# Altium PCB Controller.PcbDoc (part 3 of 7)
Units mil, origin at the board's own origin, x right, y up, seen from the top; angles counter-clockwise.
Board outline 9000 x 8000 mil, 6 copper layers (Top Layer, Layer 1, Layer 2, Layer 3, Layer 4, Bottom Layer), stack 61.699 mil thick; 761 components, 454 nets, 2369 pads, 1133 vias.
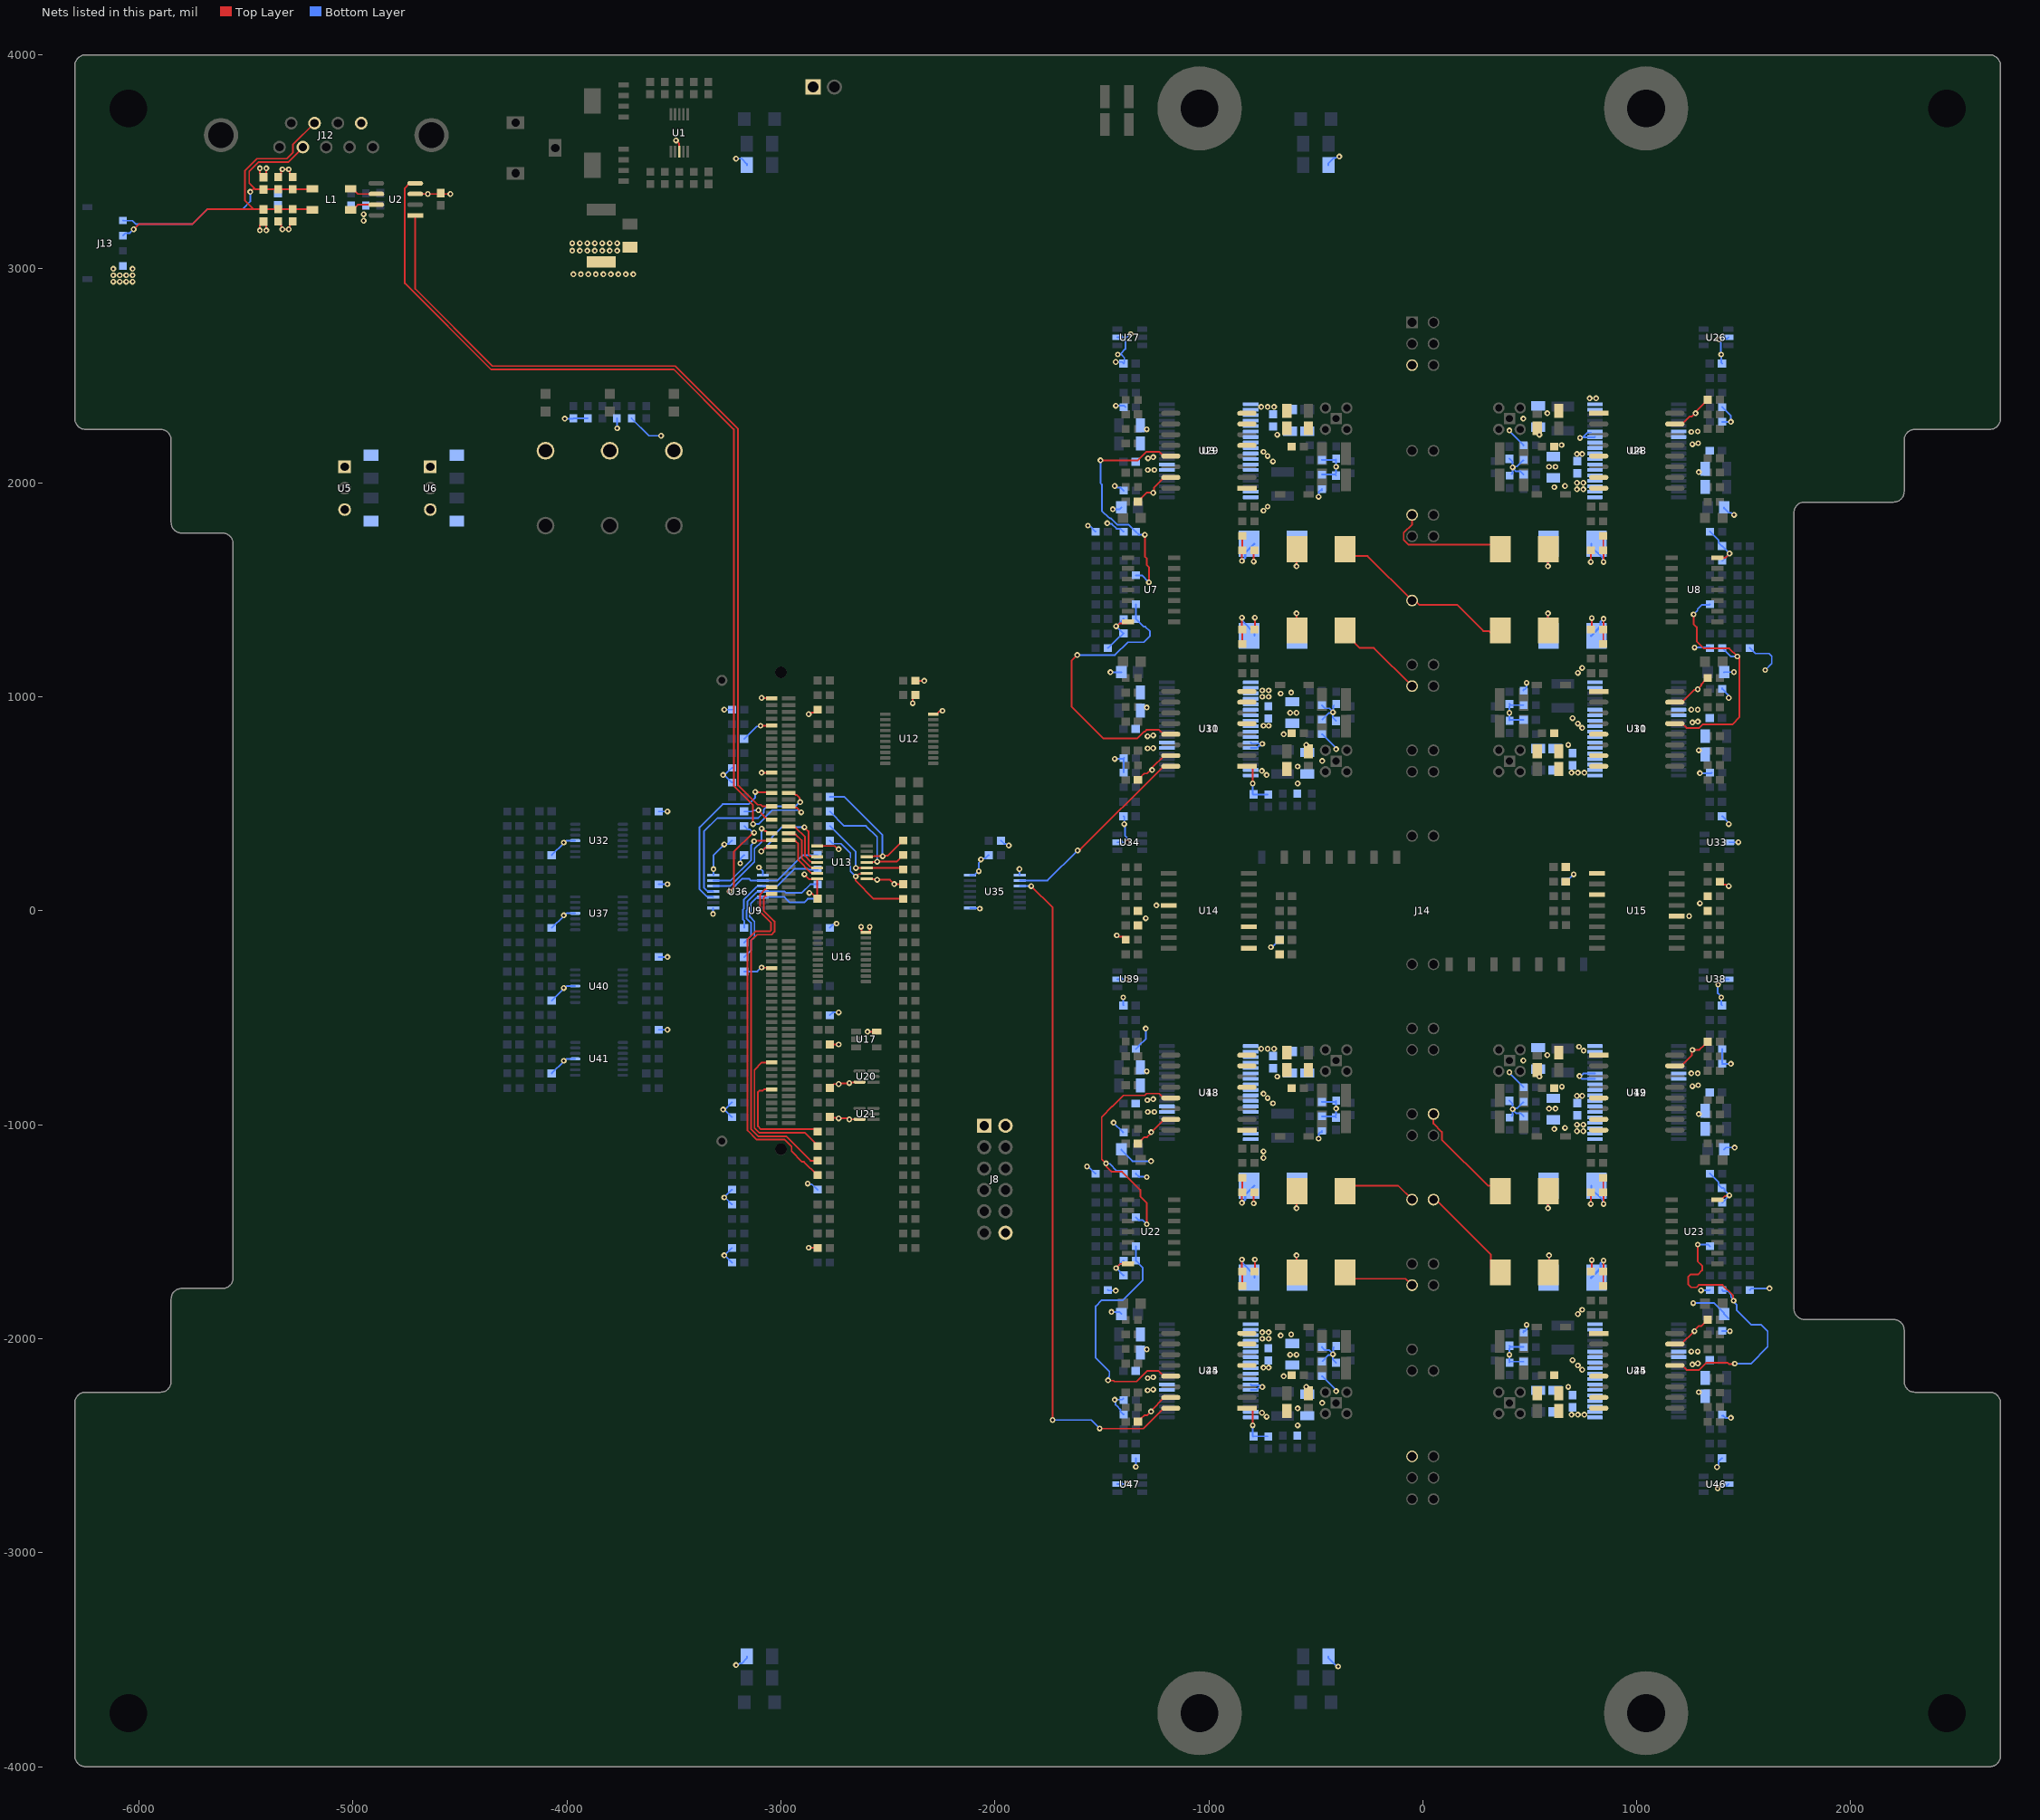
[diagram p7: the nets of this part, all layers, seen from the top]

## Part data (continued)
R171 R172: "RES SMD 4.7K OHM 1% 1/10W 0603", Case Code (Imperial)=0603, Case Code (Metric)=1608, Manufacturer="VISHAY DALE", Max Operating Temperature=155°C, Max Power Dissipation=100mW, Min Operating Temperature=-55°C, Package Quantity=5000, Power Rating=0.1W, Resistance=4.7kΩ, Resistor Type="Thick Film", Supplier Part Number 1=541-3004-6-ND, Temperature Coefficient=100ppm/°C, TOLERANCE=1%, Voltage Rating=75V
R174 R184 R212 R224 R306 R322 R362 R371: "RES SMD 107K OHM 0.1% 1/10W 0603", Case/Package=0603, Manufacturer=YAGEO, Power Rating=0.1W, Resistance=107kΩ, Temperature="-55°C to +155°C", Temperature Coefficient="25 ppm/°C", Temperature Range High=+155°C, Temperature Range Low=-55°C, TOLERANCE=0.001, Voltage Rating=75V
R175 R183 R213 R223 R307 R321 R363 R370: "RES SMD 30K OHM 0.5% 1/10W 0603", Case/Package=0603, Manufacturer=YAGEO, Power Rating=0.1W, Resistance=30kΩ, Temperature="-55°C to +155°C", Temperature Coefficient="50 ppm/°C", Temperature Range High=+155°C, Temperature Range Low=-55°C, TOLERANCE=0.005, Voltage Rating=75V
R176 R182 R214 R220 R311 R320 R364 R369: "RES SMD 49.9K OHM 1% 1/10W 0603", Case Code (Imperial)=0603, Case Code (Metric)=1608, Manufacturer=YAGEO, Max Operating Temperature=125°C, Max Power Dissipation=100mW, Min Operating Temperature=-55°C, Power Rating=0.1W, Resistance=49.9kΩ, Supplier Part Number 1=3100550, Temperature Coefficient=50ppm/°C, TOLERANCE=1%, Voltage Rating=75V, Voltage Rating (DC)=50V
R177 R181 R215 R219 R312 R318 R365 R368: "RES SMD 16.2K OHM 0.1% 1/10W", Case/Package=0603, Manufacturer=YAGEO, Power Rating=0.1W, Resistance=16.2kΩ, Temperature="-55°C to +155°C", Temperature Coefficient="25 ppm/°C", Temperature Range High=+155°C, Temperature Range Low=-55°C, TOLERANCE=0.001, Voltage Rating=75V
R186 R187 R208 R209 R324 R325 R358 R359: "RES 499 OHM 1% 1/8W 0805", Case Code (Imperial)=0805, Case Code (Metric)=2012, Manufacturer=YAGEO, Max Operating Temperature=155°C, Max Power Dissipation=0.13W, Min Operating Temperature=-55°C, Package Quantity=1, Power Rating=125mW, Resistance=499Ω, Resistor Type="Thick Film", Supplier Part Number 1=5825161, Temperature Coefficient=100ppm/°C, TOLERANCE=1%, Voltage Rating=150V
R237 R378: "RES SMD 0 OHM JUMPER 1/10W 0603", Case Code (Imperial)=0603, Case Code (Metric)=1608, Manufacturer="VISHAY DALE", Max Operating Temperature=155°C, Max Power Dissipation=100mW, Min Operating Temperature=-55°C, Package Quantity=10000, Power Rating=0.1W, Ratings=AEC-Q200, Resistance=0Ω, Resistor Type="Thick Film", Supplier Part Number 1=48P7902, Temperature Coefficient=100ppm/°C, TOLERANCE=1%, Voltage Rating=75V
R238 R379: "RES 5.1K OHM 1% 1/10W 0603", Case/Package=0603, Manufacturer=YAGEO, POWER=0.1W
R239 R240 R380 R381: "RES SMD 1.8K OHM 0.1% 1/5W 0603", Case Code (Imperial)=0603, Case Code (Metric)=1608, Manufacturer=PANASONIC, Max Operating Temperature=155°C, Max Power Dissipation=0.2W, Min Operating Temperature=-55°C, Resistance=1.8kΩ, Resistor Type="Thick Film", Temperature Coefficient=50ppm/°C, TOLERANCE=0.1%
R244 R246 R262 R264 R277 R279 R293 R300: "RES 27K OHM 1% 1/10W 0603", Case Code - mm=1608, Case/Package=0603, Manufacturer=YAGEO, Operating Temperature Range=-55Cto+155C, Package Description="2-Pin Surface Mount Device, Body 1.6 x 0.8 mm", Power Rating=0.1W, Temperature Coefficient=100PPM/C, TOLERANCE=1%, Voltage Rating=50V
R245 R247 R263 R265 R278 R280 R294 R301: library part CMP-2000-04305-1, "RES 1K OHM 5% 1/10W 0603", Case/Package=0603, Manufacturer=YAGEO, POWER=0.1W
R248 R256 R266 R271 R281 R287 R302 R310: "RES SMD 2.7K OHM 0.1% 1/10W 0603", Case/Package=0603, Manufacturer=YAGEO, Power Rating=0.1W, Resistance=2.7kΩ, Temperature="-55°C to +155°C", Temperature Coefficient="25 ppm/°C", Temperature Range High=+155°C, Temperature Range Low=-55°C, TOLERANCE=0.001, Voltage Rating=75V
R260 R267: "RES SMD 5.62KOHM 0.1% 1/10W 0603", Case/Package=0603, Manufacturer=PANASONIC, Max Operating Temperature=155°C, Min Operating Temperature=-55°C, Package Height=0.45mm, Package Length=1.6mm, Package Width=0.8mm, POWER=0.1W, Rated Temperature=85°C, Resistor Type="FIXED RESISTOR", Supplier Part Number=667-ERA-3AEB5621V, Temperature Coefficient (ppm/Cel)=25, TOLERANCE=0.1%, Working Voltage=75V
R284: "RES 5.49K OHM 1% 1/10W 0603", Case Code (Imperial)=0603, Case Code (Metric)=1608, Manufacturer=YAGEO, Max Operating Temperature=155°C, Max Power Dissipation=100mW, Min Operating Temperature=-55°C, Package Quantity=5000, Power Rating=0.1W, Resistance=5.49kΩ, Supplier Part Number 1=1172345, Temperature Coefficient=100ppm/°C, TOLERANCE=1%, Voltage Rating=50V
TP1 TP2 TP3: library part CMP-1672-00002-4, "PC TEST POINT MULTIPURPOSE RED", Case/Package=N/A, Colour=Red, Manufacturer=KEYSTONE, Package Quantity=100
TP4 TP5 TP6: library part CMP-1672-00003-4, "PC TEST POINT MULTIPURPOSE BLACK", Case/Package=N/A, Colour=Black, Manufacturer=KEYSTONE, Package Quantity=100
U1: "IC SURGE SUPPRESSION ADJ 10MSOP", Case/Package=10-MSOP, Manufacturer="ANALOG DEVICES", Supplier Part Number 1=505-LTC4368IMS-2#PBF-ND
U2: library part CMP-04872-000112-1, "IC TRANSCEIVER 1/1 8SOIC", Case/Package=8-SOIC, Manufacturer="TEXAS INSTRUMENTS"
U3 U4 U10 U11 U18 U19 U24 U25: library part CMP-00024-00019-13, "DGTL ISO 5.7KV 1CH GT DVR 16SOIC", Case/Package=16-SOIC, Manufacturer="TEXAS INSTRUMENTS", Max Operating Temperature=125°C, Min Operating Temperature=-40°C
U5: "DC DC CONVERTER 3.3V 3W", Case/Package=SIP, Manufacturer=RECOM, Max Input Voltage=28V, Max Operating Temperature=85°C, Max Output Current=1A, Max Output Power=3.3W, Max Output Voltage=3.3V, Max Power Dissipation=3W, Min Input Voltage=8V, Min Input Voltage (DC)=7V, Min Operating Temperature=-40°C, Package=3-SIP, Supplier Part Number 1=9176626
U6: "DC DC CONVERTER 5V 5W", Case/Package=SIP, Current - Output 1=1A, Manufacturer=RECOM, Max Input Voltage=28V, Max Operating Temperature=85°C, Max Output Voltage=5V, Max Power Dissipation=5W, Min Input Voltage=8V, Min Operating Temperature=-40°C, Package=3-SIP, Package Quantity=42, Supplier Part Number 1=1446013
U7 U8 U22 U23: "IC GATE AND 2CH 4-INP 14SOIC", Case/Package=8-SOIC, Manufacturer="TEXAS INSTRUMENTS"
U9: "EVAL BOARD FOR TMS320F280039C", Case/Package=N/A, Manufacturer="TEXAS INSTRUMENTS", Supplier Part Number 1=595-TMDSCNCD280039C
U12 U16: library part CMP-0440-01163-3, "IC BUF NON-INVERT 5.5V 20TSSOP", Case/Package=20-TSSOP, F @ Nom Voltage(Max)(Mhz)=110, Generic Part Number=SN74LV541AT, ICC @ Nom Voltage(Max)(mA)=0.02, Manufacturer="TEXAS INSTRUMENTS", Operating Temperature Range(C)="-40 to 125", Rating=Catalog, tpd @ Nom Voltage(Max)(ns)=7.9, Voltage(Nom)(V)=5
U13 U35 U36: "IC TRANSLATOR UNIDIR 14TSSOP", Case/Package=14-TSSOP, Manufacturer="TEXAS INSTRUMENTS"
U14 U15: "IC ISOLATED AMPLIFIER", Case/Package=16-SOIC, Manufacturer="TEXAS INSTRUMENTS"
U17: library part CMP-0384-02059-2, "IC OPAMP GP 1 CIRCUIT TSOT23-5", Amplifiers Per Package=1, Case/Package=TSOT-23-5, Generic Part Number=AD8615, Input Bias Current=200fA, Input Offset Voltage=80uV, Manufacturer="ANALOG DEVICES"
U20 U21: library part CMP-04895-000486-1, "IC OPAMP GP 1 CIRCUIT SC70-5", Case/Package=SC-70-5, Input Bias Current=1pA, Input Offset Voltage (Vos)=750uV, Manufacturer="TEXAS INSTRUMENTS", Max Operating Temperature=125°C, Min Operating Temperature=-40°C, Operating Supply Current=75uA, Output Current per Channel=15mA
U26 U27 U33 U34 U38 U39 U46 U47: library part CMP-0859-00232-4, "IC INVERTER 2CH 2-INP SOT23-6", Case/Package=SOT-23-6, F @ Nom Voltage(Max)(Mhz)=150, Generic Part Number=SN74LVC2G14, ICC @ Nom Voltage(Max)(mA)=0.01, Manufacturer="TEXAS INSTRUMENTS", Operating Temperature Range(C)="-40 to 125", Rating=Catalog, tpd @ Nom Voltage(Max)(ns)=9.5,5.7,5.4,4.3, Voltage(Nom)(V)=1.8,2.5,3.3,5
U28 U29 U30 U31 U42 U43 U44 U45: "DUAL DC DC CONVERTER 1.5W", Case/Package=36-BSSOP, Manufacturer="TEXAS INSTRUMENTS", Max Supply Voltage=27V, Min Supply Voltage=21V, Operating Temperature Range="-40°C to +150°C", Output Voltage=18-25/2.5-25V, Part Number=UCC14240DWNQ1
U32 U37 U40 U41: library part CMP-0384-01836-1, "IC CMOS 4 CIRCUIT 14TSSOP", Amplifiers Per Package=4, Case/Package=14-TSSOP, Generic Part Number=AD8618, Input Bias Current=200fA, Input Offset Voltage=23uV, Manufacturer="ANALOG DEVICES"

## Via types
v1: diameter 27, hole 13, Top Layer to Bottom Layer, tented both sides, 1133 vias

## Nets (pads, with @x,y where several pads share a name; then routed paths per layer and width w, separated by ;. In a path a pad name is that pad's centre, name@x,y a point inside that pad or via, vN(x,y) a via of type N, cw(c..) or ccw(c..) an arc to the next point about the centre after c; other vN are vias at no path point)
+3.3V: C44.1 C56.1 C64.1 C67.1 C114.1 C164.1 C165.1 J8.1 R41.2 R47.2 R137.2 R161.2 R168.2 R218.2 R230.2 R234.2 R242.2 R258.2 R272.2 R284.2 R289.2 R314.2 R319.2 R334.2 R335.2 R338.2 R348.2 R352.2 TP3.1 U5.3 U13.8 U13.14 U17.5 U20.5 U21.5 U35.8 U35.14 U36.8 U36.14 | length 2182.5
  Top Layer w8: v1(-2890,170) -2866.84,146.84 -2833.64,146.84 U13.14@-2831.25,149.23 -2831.25,58.67 -2832.2,58.67 -2853.2,79.67 -2863.21,79.67 v1(-2866.84,83.3) ; v1(-2870,-1575) -2829.62,-1575 R137.2@-2828.62,-1576 ; v1@-2866.84,86.84 v1@-2865.07,85.07 ; -2857.2,926.04 -2842.58,926.04 R47.2@-2828.62,940 ; -2831.65,113.37 -2831.65,113.75 ; U13.8@-2831.25,302.77 -2749.91,302.77 -2735.14,288 v1(-2730,288) ; C67.1@-2771.42,-964 -2767.92,-967.5 -2732.5,-967.5 v1(-2730,-970) -2690.14,-970 -2685.14,-975 v1(-2680,-975) -2679.8,-974.8 -2616.64,-974.8 U21.5@-2616.43,-975 ; C64.1@-2771.42,-828 -2770.47,-828 -2752.47,-810 v1(-2730,-810) -2727.5,-807.5 -2682.5,-807.5 v1(-2680,-805) -2676.89,-801.89 -2625.28,-801.89 U20.5@-2623.98,-800.59 ; C56.1@-2771.42,-624 -2770.42,-625 v1(-2730,-625) ; v1(-2595,-565) -2553.17,-565 U17.5@-2551.77,-563.6 ; R41.2@-2371.38,1076 -2370.38,1075 v1(-2330,1075)
  Bottom Layer w8: R168.2@-3698,2301.38 -3698,2300.47 -3617.53,2220 v1(-3560,2220) ; R289.2@-3571.38,-556 v1(-3530,-556) ; R272.2@-3571.38,-216 v1(-3530,-216) ; R258.2@-3571.38,124 v1(-3530,124) ; R242.2@-3571.38,464 v1(-3530,464) ; v1(-3317,-15) -3317,12.48 U36.8@-3316.25,13.23 ; U36.14@-3316.25,166.77 -3314.86,168.16 v1(-3314.86,194.59) -3314.86,260.14 v1(-3265,310) -3261.86,313.14 -3243.44,313.14 C164.1@-3228.58,328 ; v1(-3265,-1610) v1@-3263.53,-1610 ; v1(-3265,940) R218.2@-3228.62,940 ; R352.2@-3228.62,-1644 -3229.53,-1644 v1@-3263.53,-1610 ; R348.2@-3228.62,-1576 -3229.53,-1576 v1@-3263.53,-1610 ; R338.2@-3228.62,-1372 -3229.53,-1372 -3261.53,-1340 v1(-3265,-1340) -3265,-1339.47 -3229.53,-1304 R335.2@-3228.62,-1304 ; R319.2@-3228.62,-964 -3229.53,-964 -3260.89,-932.64 -3266.36,-932.64 v1(-3270,-929) -3266.36,-925.36 -3259.89,-925.36 -3229.53,-895 R314.2@-3228.62,-895 ; R234.2@-3228.62,600 -3229.53,600 -3260.89,631.36 -3266.36,631.36 v1(-3270,635) -3266.36,638.64 -3258.89,638.64 -3229.53,668 R230.2@-3228.62,668 ; v1(-2875,-1275) -2871.36,-1278.64 -2854.89,-1278.64 -2829.53,-1304 R334.2@-2828.62,-1304 ; v1(-2869.74,918.64) v1@-2866.11,915 ; R284.2@-2771.38,-488 -2758.38,-475 v1(-2730,-475) ; U35.8@-2116.25,13.23 -2114.64,11.61 -2071.61,11.61 v1(-2070,10) ; U35.14@-2116.25,166.77 -2095.5,166.77 -2077.27,185 v1(-2075,185) -2075,224.86 -2065,234.86 v1(-2065,240) -2059.86,240 -2054.72,245.14 -2043.44,245.14 C165.1@-2028.58,260
+5V: C4.1 C7.1 C18.1 C23.1 C26.1 C37.1 C42.1 C43.1 C45.1 C48.1 C49.1 C55.1 C69.1 C75.1 C86.1 C89.1 C90.1 C113.1 C115.1 C128.1 C142.1 C155.1 C157.1 C158.1 C162.1 C166.1 C168.1 C178.1 C181.1 C187.1 C193.1 C194.1 C195.1 C211.1 C231.1 C247.1 C269.1 C270.1 J8.2 J12.9 J14.005 J14.107 R69.2 R80.2 R160.2 R164.1 R165.1 R169.2 R173.2 R185.2 R186.2 R187.2 R188.2 R189.2 R190.2 R193.2 R202.2 R205.2 R206.2 R207.2 R208.2 R209.2 R211.2 R228.2 R231.1 R232.1 R295.1 R297.1 R303.2 R323.2 R324.2 R325.2 R327.2 R328.2 R329.2 R336.2 R350.2 R355.2 R356.2 R357.2 R358.2 R359.2 R361.2 R373.2 R374.1 R375.1 TP2.1 U2.3 U3.15 U4.15 U6.3 U7.14 U8.14 U9.48 U9.84 U9.98 U9.112 U9.120 U10.15 U11.15 U12.20 U13.1 U14.12 U15.12 U16.20 U18.15 U19.15 U22.14 U23.14 U24.15 U25.15 U26.5 U27.5 U32.4 U33.5 U34.5 U35.1 U36.1 U37.4 U38.5 U39.5 U40.4 U41.4 U46.5 U47.5 | length 8021
  Top Layer w8: U2.3@-4708.91,3350 v1(-4650,3350) -4593.58,3350 C4.1@-4590,3353.58 -4586.42,3350 v1(-4545,3350) ; v1(-3105,470) -3105,469.36 -3080.9,445.26 -3080.9,441.88 -3073.87,434.85 -3068.71,434.85 -3059.06,425.2 U9.84@-3042.32,425.2 ; v1(-3095,865) -3094.43,865.57 -3042.89,865.57 U9.112@-3042.32,866.14 ; v1(-3090,-265) -3088.64,-266.36 -3043.68,-266.36 U9.48@-3042.32,-267.72 ; v1(-3090,645) -3089.67,645.33 -3042.66,645.33 U9.98@-3042.32,645.67 ; v1(-3090,995) -3088.56,993.56 -3043.76,993.56 U9.120@-3042.32,992.13 ; v1(-2625,-75) -2622.42,-77.58 -2622.42,-96.97 -2618.54,-100.84 U16.20@-2602.8,-100.84 -2588.94,-100.84 -2585.07,-96.97 -2585.07,-75.07 v1(-2585,-75) ; U13.1@-2598.75,149.23 -2596.64,147.11 -2552.11,147.11 v1(-2550,145) -2490,145 v1(-2470,125) -2429.58,125 C42.1@-2428.58,124 ; v1(-2383.76,970) -2383.76,1005.66 C26.1@-2381.42,1008 ; U12.20@-2287.8,919.16 -2272.05,919.16 -2259.84,931.36 -2248.14,931.36 v1(-2245,934.5) ; v1(-1433.53,-1670) -1413.53,-1650 U22.14@-1377.25,-1650 ; v1(-1433.53,1330) -1428.39,1330 -1415.39,1343 -1384.25,1343 U7.14@-1377.25,1350 ; v1(-1430,-115) -1424.86,-115 -1417.81,-122.04 -1402.58,-122.04 R80.2@-1388.62,-136 ; C86.1@-1331.42,-2388 -1330.47,-2388 -1315.61,-2373.14 -1315.61,-2372.19 -1301.74,-2358.32 -1288.32,-2358.32 v1(-1270,-2340) -1270,-2336.68 -1208.32,-2275 U24.15@-1177.78,-2275 ; C69.1@-1331.42,-1088 -1330.47,-1088 -1315.61,-1073.14 -1315.61,-1072.19 -1301.74,-1058.32 -1288.32,-1058.32 -1269.78,-1039.78 v1(-1269.78,-1035) ; C37.1@-1331.42,612 -1330.47,612 -1315.61,626.86 -1315.61,627.81 -1301.74,641.68 -1288.32,641.68 v1@-1268.42,661.58 ; C18.1@-1331.42,1912 -1330.47,1912 -1315.61,1926.86 -1315.61,1927.81 -1288.42,1955 -1261.5,1955 v1(-1260,1953.5) ; v1@-1267.39,-1037.39 -1265,-1035 -1265,-1031.68 -1208.32,-975 U18.15@-1177.78,-975 ; v1(-1265,658.16) v1@-1268.42,661.58 ; v1@-1260,1955 -1256.36,1958.64 -1256.36,1976.96 -1208.32,2025 U3.15@-1177.78,2025 ; U10.15@-1177.78,725 -1208.32,725 -1265,668.32 -1265,665 v1@-1268.42,661.58 ; U25.15@1177.78,-2025 1208.32,-2025 1268.32,-1965 v1(1269.78,-1965) ; U19.15@1177.78,-725 1208.32,-725 1257.82,-675.5 1257.82,-652.18 v1(1260,-650) 1293.42,-650 1315.61,-627.81 1315.61,-626.86 1330.47,-612 C55.1@1331.42,-612 ; U11.15@1177.78,975 1211.65,975 1268.01,1031.36 1281.36,1031.36 v1(1285,1035) 1285,1035.92 1302.57,1053.49 1302.57,1059.15 1315.61,1072.19 1315.61,1073.14 1330.47,1088 C23.1@1331.42,1088 ; U4.15@1177.78,2275 1211.65,2275 1246.48,2309.83 1257.03,2309.83 1272.7,2325.5 v1(1275.24,2325.5) ; v1@1267.39,-1962.61 1288.32,-1941.68 1301.74,-1941.68 1315.61,-1927.81 1315.61,-1926.86 1330.47,-1912 C75.1@1331.42,-1912 ; v1@1275,2325.14 1278.82,2328.96 1278.82,2336.35 1330.47,2388 C7.1@1331.42,2388 ; U23.14@1377.25,-1350 1395,-1350 1411.36,-1333.64 1428.94,-1333.64 v1(1432.58,-1330) ; U8.14@1377.25,1650 1415,1650 1433.53,1668.53 v1(1433.53,1670) ; R69.2@1388.62,136 1402.58,122.04 1417.81,122.04 1424.86,115 v1(1430,115)
  Bottom Layer w8: C211.1@-4071.42,-760 -4070.47,-760 -4015,-704.53 v1(-4015,-701) -4009.86,-701 -4000.86,-692 U41.4@-3961.22,-692 ; C193.1@-4071.42,-420 -4070.47,-420 -4015,-364.53 v1(-4015,-361) -4009.86,-361 -4000.86,-352 U40.4@-3961.22,-352 ; C181.1@-4071.42,-80 -4070.47,-80 -4015,-24.53 v1(-4015,-21) -4009.86,-21 -4000.86,-12 U37.4@-3961.22,-12 ; C168.1@-4071.42,260 -4070.47,260 -4015,315.47 v1(-4015,319) -4009.86,319 -4000.86,328 U32.4@-3961.22,328 ; R169.2@-3766,2301.38 -3765,2300.38 v1(-3765,2255) ; v1(-3190.21,221.63) -3187.24,224.6 -3187.24,245.14 -3172.37,260 C166.1@-3171.42,260 ; C187.1@-3171.42,-284 -3110.06,-284 -3091.06,-265 v1(-3090,-265) -3093.64,-261.36 v1@-3093.64,-255.41 ; C155.1@-3171.42,464 -3135.88,464 -3130.5,469.38 -3105.62,469.38 v1(-3105,470) ; C142.1@-3171.42,804 -3170.47,804 -3113.11,861.36 -3098.64,861.36 v1(-3095,865) ; v1(-3102.5,202.5) -3083.75,183.75 U36.1@-3083.75,166.77 ; v1@-3090,640.47 v1(-3090,645) ; C178.1@-2771.42,-80 -2756.56,-65.14 -2745.28,-65.14 v1(-2740,-59.86) ; C162.1@-1971.42,328 -1956.56,313.14 -1948.28,313.14 -1940.14,305 v1(-1935,305) ; v1(-1885,195) -1885,168.02 U35.1@-1883.75,166.77 ; v1(-1569.5,-1195) -1565.86,-1198.64 -1558.89,-1198.64 -1529.53,-1228 R329.2@-1528.62,-1228 ; v1(-1565,1800) -1561.36,1796.36 -1553.89,1796.36 -1529.53,1772 R190.2@-1528.62,1772 ; v1(-1474.77,1811.46) -1471.14,1807.82 -1453.41,1807.82 -1431.55,1785.96 -1413.48,1785.96 -1399.53,1772 R189.2@-1398.62,1772 ; R357.2@-1471.38,-1772 -1468.38,-1775 v1(-1435,-1775) ; R207.2@-1471.38,1228 -1470.47,1228 -1417.34,1281.14 -1413.44,1281.14 C128.1@-1398.58,1296 -1399.53,1296 v1(-1433.53,1330) -1399.53,1364 R202.2@-1398.62,1364 ; v1(-1460,1115) R209.2@-1408.46,1115 ; v1(-1455,-1875) -1418.46,-1875 R359.2@-1408.46,-1885 ; v1(-1448.93,1876.94) -1416.52,1876.94 R187.2@-1408.46,1885 ; v1(-1445,-990) -1445,-991.53 -1401.53,-1035 R323.2@-1400,-1035 ; v1(-1440,710) R228.2@-1400,710 ; v1(-1439.5,1985) -1434.36,1985 -1426.31,1976.96 -1412.58,1976.96 R185.2@-1398.62,1963 ; v1(-1435,2565) -1405.58,2565 C90.1@-1398.58,2558 -1395,2561.58 -1395,2585 -1410,2600 v1@-1415,2600 ; v1(-1434.47,2360) -1395,2360 R165.1@-1390,2355 ; U47.5@-1428.07,-2680 -1427.46,-2679.38 -1381.85,-2679.38 v1(-1381.23,-2678.77) ; U39.5@-1428.07,-320 v1(-1385,-320) ; U34.5@-1428.07,320 v1(-1380,320) -1383.64,323.64 -1383.64,342.57 -1392.45,351.39 -1392.45,402.45 v1(-1395,405) -1395,438.42 C158.1@-1398.58,442 ; U27.5@-1428.07,2680 -1389.69,2680 ; v1(-1425.5,2600) -1423,2602.5 -1412.5,2602.5 -1389.69,2625.31 -1389.69,2680 ; R325.2@-1408.46,-1115 -1408.46,-1119.02 -1357.48,-1170 v1(-1270,-1170) ; R373.2@-1400,-2280 -1405,-2285 -1435,-2285 -1436.36,-2286.36 -1436.36,-2307.57 -1429.5,-2314.44 -1413.17,-2330.76 -1413.17,-2340.04 -1399.22,-2354 R375.1@-1398.62,-2354 ; v1(-1400,-405) -1400,-440.58 C195.1@-1398.58,-442 ; C247.1@-1398.58,-1704 -1399.53,-1704 v1(-1433.53,-1670) -1399.53,-1636 R350.2@-1398.62,-1636 ; R232.1@-1398.62,646 -1398.62,708.62 R228.2@-1400,710 ; R228.2@-1395,715 R228.2@-1400,710 ; v1(-1365,2695) -1370.14,2695 -1385.14,2680 -1389.69,2680 ; C270.1@-1341.42,-2558 -1341.23,-2558.19 v1(-1341.23,-2598.77) ; R328.2@-1341.38,-1228 -1327.42,-1241.96 -1293.04,-1241.96 v1(-1290,-1245) ; R297.1@-1341.38,-646 -1340.47,-646 -1326.52,-632.04 -1326.52,-631.14 -1295,-599.62 v1@-1295,-555 ; v1(1263.77,-1833.77) 1361.25,-1833.77 1408.46,-1880.98 R358.2@1408.46,-1885 R358.2@1429.15,-1905.68 ; v1(1270,1230) R206.2@1340.28,1230 ; v1(1295.24,643.17) 1348.17,643.17 R231.1@1350,645 ; v1(1300.48,-1774.42) 1337.8,-1774.42 1338.38,-1775 R356.2@1341.38,-1772 ; R327.2@1341.38,-1228 1342.28,-1228 1382.76,-1268.48 1382.76,-1281.14 1397.63,-1296 C231.1@1398.58,-1296 1406,-1296 1410,-1300 1410,-1306.47 1432.58,-1329.05 v1(1432.58,-1330) 1432.58,-1330.95 1399.53,-1364 R336.2@1398.62,-1364 ; R188.2@1341.38,1772 1342.28,1772 1382.76,1731.52 1382.76,1718.86 1397.63,1704 C115.1@1398.58,1704 1399.53,1704 v1(1433.53,1670) 1399.53,1636 R193.2@1398.62,1636 ; v1(1375,-2600) 1375,-2594.86 1382.76,-2587.09 1382.76,-2572.86 1397.63,-2558 C269.1@1398.58,-2558 ; v1(1377.98,-2700) 1383.12,-2700 1394.33,-2688.8 1419.28,-2688.8 U46.5@1428.07,-2680 ; R361.2@1398.62,-1963 1400.62,-1965 v1(1435,-1965) ; R295.1@1398.62,-646 1398.62,-708.62 R303.2@1400,-710 ; C194.1@1398.58,-442 1395,-438.42 1395,-401.67 1378.64,-385.3 1378.64,-346.36 v1(1380,-345) 1383.65,-345 1399.86,-328.8 1408.45,-328.8 1417.24,-320 U38.5@1428.07,-320 ; C157.1@1398.58,442 1399.53,442 1426.36,415.16 1426.36,408.77 v1(1430,405.14) ; R164.1@1398.62,2354 1399.53,2354 1439.5,2314.03 1439.5,2285.5 v1(1440,2285) ; C89.1@1398.58,2558 1394.53,2562.05 v1(1394.53,2600) 1392.45,2602.08 1392.45,2656.94 1384.53,2664.86 v1(1384.53,2670) 1388.16,2673.64 1421.71,2673.64 U26.5@1428.07,2680 ; R374.1@1400,-2360 1405.53,-2360 1415.53,-2370 v1(1440,-2370) ; R303.2@1400,-715 v1(1440,-715) ; R211.2@1400,1040 1400,1036.53 1426.36,1010.16 1426.36,998.64 v1(1430,995) ; R173.2@1400,2285 v1@1435,2285 ; R324.2@1408.46,-1115 1417.03,-1106.44 v1(1457.5,-1106.44) ; R208.2@1408.46,1115 1408.9,1115.44 v1(1454.5,1115.44) ; R186.2@1408.46,1885 1408.46,1880.98 1429.23,1860.22 1439.64,1860.22 1449.86,1850 v1(1455,1850) ; U33.5@1433.07,320 1433.14,320.07 1474.93,320.07 v1(1475,320.14) ; R355.2@1528.62,-1772 1535.62,-1765 v1(1620.5,-1765) ; R205.2@1528.62,1228 1529.53,1228 1555.35,1202.18 1619.13,1202.18 1631,1190.31 1631,1155.5 v1(1600.5,1125)
  other v1: -1440,-2285 -1295,-550 1395,-405 -1295,-35 1245,-25 -1245,25 1295,35 -4950,3225 -4950,3255
+12V: C6.1 C97.1 C99.1 C101.1 C102.1 C103.1 C106.1 C108.1 C112.1 C129.1 C135.1 C137.1 C140.1 C141.1 C146.1 C208.1 C213.1 C217.1 C220.1 C222.1 C227.1 C248.1 C254.1 C255.1 C258.1 C259.1 C263.1 J1.1 J8.12 J13.1 R13.2 R158.1 R159.1 R171.2 R172.2 R382.1 R383.1 TP1.1 U1.8 U5.1 U6.1 U28.6 U28.7 U29.6 U29.7 U30.6 U30.7 U31.6 U31.7 U42.6 U42.7 U43.6 U43.7 U44.6 U44.7 U45.6 U45.7 | length 447.3
  Top Layer w8: v1(-3490,3600) -3475,3585 U1.8@-3475,3547.91
  Bottom Layer w8: v1(-4010,2300) -3971.38,2300 R172.2@-3970,2301.38 R171.2@-3902,2301.38 ; v1(-3210,-3525) -3206.36,-3521.36 -3195.47,-3521.36 -3191.68,-3517.58 -3183.76,-3517.58 -3159.1,-3492.92 R383.1@-3159.1,-3485 ; v1(-3210,3515) -3183.76,3515 -3159.1,3490.34 R159.1@-3159.1,3485 ; R382.1@-440.9,-3485 -440.9,-3492.92 -405.31,-3528.51 -398.97,-3528.51 v1(-395.34,-3532.15) ; R158.1@-440.9,3485 -440.9,3492.92 -416.24,3517.58 -408.32,3517.58 -404.53,3521.36 -393.64,3521.36 v1(-390,3525)
  other v1: 1290,-2250 -1286.73,-2241.27 -1260.03,-2237.83 -1285.8,-2184.2 -1260,-2180 1260,-2120 1285.54,-2115.54 1254.98,-2060.18 1285,-2060 -1290,-2050 1290,-950 -1285,-940 -1255,-940 -1287.15,-884.88 -1260,-880 1260,-820 1287.15,-815.12 1255,-760 1285,-760 -1290,-750 1290,750 -1286.73,758.73 -1260,760.16 -1286.16,815.72 -1260,820 1260,880 1285.54,884.46 1255,940 1285,940 -1290,950 1290,2050 -1285,2060 -1255,2060 -1284.47,2114.47 -1260,2120 1260,2180 1287.15,2184.88 1254.49,2237.94 1285,2240 -1290,2250 -6120,2940 -6090,2940 -6060,2940 -6030,2940 -6120,2970 -6090,2970 -6060,2970 -6030,2970 -3970,2975 -3935,2975 -3900,2975 -3865,2975 -3830,2975 -3795,2975 -3760,2975 -3725,2975 -3690,2975 -6120,3000 -6030,3000 -3975,3085 -3940,3085 -3905,3085 -3870,3085 -3835,3085 -3800,3085 -3765,3085 -3975,3120 -3940,3120 -3905,3120 -3870,3120 -3835,3120 -3800,3120 -3765,3120
+15V_1P: C33.1 C144.1 C145.1 C148.1 R35.2 R212.2 U11.5 U30.28 U30.29 | length 95.3
  Top Layer w8: R35.2@786.38,1315 790,1318.62 v1(790,1367.52)
  Bottom Layer w8: R212.2@470,1035 477.04,1035 485,1042.96 v1(485,1065) ; R212.2@470.47,1029 R212.2@471.38,1029
  other v1: 680,775 745,855 725,875
+15V_1S: C82.1 C261.1 C262.1 C264.1 R139.2 R362.2 U25.5 U44.28 U44.29 | length 95.3
  Top Layer w8: R139.2@786.38,-1685 790,-1681.38 v1(790,-1632.48)
  Bottom Layer w8: R362.2@470,-1965 477.04,-1965 485,-1957.04 v1(485,-1935) ; R362.2@470.47,-1971 R362.2@471.38,-1971
  other v1: 680,-2225 745,-2145 725,-2125
+15V_2P: C35.1 C132.1 C134.1 C149.1 R34.2 R224.2 R238.2 U10.5 U31.28 U31.29 | length 153.6
  Top Layer w8: R34.2@-786.38,1315 -785,1316.38 v1(-785,1370)
  Bottom Layer w8: R224.2@-471.38,825 -470.47,825 -405,759.53 v1(-405,755)
  other v1: -585,595 -584.69,674.49 -745,865 -720.5,865 -615,1020
+15V_2S: C84.1 C251.1 C253.1 C265.1 R138.2 R371.2 R379.2 U24.5 U45.28 U45.29 | length 153.6
  Top Layer w8: R138.2@-786.38,-1685 -785,-1683.62 v1(-785,-1630)
  Bottom Layer w8: R371.2@-471.38,-2175 -470.47,-2175 -405,-2240.47 v1(-405,-2245)
  other v1: -585,-2405 -584.7,-2325.5 -745,-2135 -720.5,-2135 -615,-1980
+15V_3P: C11.1 C94.1 C95.1 C96.1 R32.2 R184.2 U3.5 U29.28 U29.29 | length 96.8
  Top Layer w8: v1(-790,1632.48) -790,1681.38 R32.2@-786.38,1685
  Bottom Layer w8: v1(-486.96,1935) -486.24,1935.73 -486.24,1957.04 -478.28,1965 R184.2@-470,1965 ; R184.2@-471.38,1971 R184.2@-470.47,1971
  other v1: -725,2125 -745,2145 -680,2225
+15V_3S: C60.1 C205.1 C206.1 C207.1 R129.2 R322.2 U18.5 U43.28 U43.29 | length 96.8
  Top Layer w8: v1(-790,-1367.52) -790,-1318.62 R129.2@-786.38,-1315
  Bottom Layer w8: v1(-486.96,-1065) -486.24,-1064.27 -486.24,-1042.96 -478.28,-1035 R322.2@-470,-1035 ; R322.2@-471.38,-1029 R322.2@-470.47,-1029
  other v1: -725,-875 -745,-855 -680,-775
+15V_4P: C9.1 C93.1 C104.1 C107.1 R33.2 R174.2 U4.5 U28.28 U28.29 | length 153.6
  Top Layer w8: v1(785,1630) 785,1683.62 R33.2@786.38,1685
  Bottom Layer w8: v1(405,2245) 405,2240.47 470.47,2175 R174.2@471.38,2175
  other v1: 615,1980 720.5,2135 745,2135 581.88,2325.5
+15V_4S: C58.1 C204.1 C218.1 C221.1 R130.2 R306.2 U19.5 U42.28 U42.29 | length 153.6
  Top Layer w8: v1(785,-1370) 785,-1316.38 R130.2@786.38,-1315
  Bottom Layer w8: v1(405,-755) 405,-759.53 470.47,-825 R306.2@471.38,-825
  other v1: 615,-1020 720.5,-865 745,-865 581.88,-674.5
-4V_1P: C33.2 C36.2 C130.2 C138.2 C144.2 C148.2 R215.1 R220.1 U11.8 U30.19 U30.20 U30.21 U30.22 U30.23 U30.24 U30.25 U30.26 U30.27 U30.30 U30.31 U30.35 U30.36 | length 196.4
  Bottom Layer w8: R220.1@405,890 408,893 C138.2@471.42,893 C138.2@471.42,893 ; R220.1@405,895 v1(405,925) C130.2@405,955 ; C130.2@405,966.42 410.42,961 R215.1@471.38,961
  other v1: 695,645 725,645 755,645 700,900 725,1111.5 745,1135
-4V_1S: C82.2 C85.2 C249.2 C256.2 C261.2 C264.2 R365.1 R369.1 U25.8 U44.19 U44.20 U44.21 U44.22 U44.23 U44.24 U44.25 U44.26 U44.27 U44.30 U44.31 U44.35 U44.36 | length 196.4
  Bottom Layer w8: R369.1@405,-2110 408,-2107 C256.2@471.42,-2107 C256.2@471.42,-2107 ; R369.1@405,-2105 v1(405,-2075) C249.2@405,-2045 ; C249.2@405,-2033.58 410.42,-2039 R365.1@471.38,-2039
  other v1: 695,-2355 725,-2355 755,-2355 700,-2100 725,-1885 745,-1865
-4V_2P: C32.2 C132.2 C133.2 C134.2 C139.2 C149.2 R214.1 R219.1 U10.8 U31.19 U31.20 U31.21 U31.22 U31.23 U31.24 U31.25 U31.26 U31.27 U31.30 U31.31 U31.35 U31.36 | length 306.3
  Bottom Layer w8: U31.31@-804.13,760.43 -776.57,760.43 -765.64,771.36 -757.69,771.36 -750,779.05 v1(-750,780) ; U31.30@-804.13,786.02 -799.28,781.17 v1@-761.31,781.17 ; C133.2@-471.42,961 -456.56,946.14 -436.14,946.14 v1@-425,935 ; R219.1@-470,895 -468.47,895 -439.61,923.86 -423.64,923.86 v1(-420,927.5) -418.96,928.54 -418.96,956.04 R214.1@-415,960 ; v1@-419.86,924.86 -419.86,902.44 C139.2@-405,887.58
  other v1: -730,635 -751.87,653.64 -470,700 -545,775 -620,925 -590,925 -750,1000 -720.5,1000 -750,1030 -720.5,1030
-4V_2S: C81.2 C251.2 C252.2 C253.2 C257.2 C265.2 R364.1 R368.1 U24.8 U45.19 U45.20 U45.21 U45.22 U45.23 U45.24 U45.25 U45.26 U45.27 U45.30 U45.31 U45.35 U45.36 | length 303.5
  Bottom Layer w8: U45.31@-804.13,-2239.57 -776.57,-2239.57 -765.64,-2228.64 -753.14,-2228.64 v1(-750,-2225.5) ; U45.30@-804.13,-2213.98 -799.28,-2218.83 v1@-761.31,-2218.83 ; C252.2@-471.42,-2039 -456.56,-2053.86 -436.14,-2053.86 v1@-425,-2065 ; R368.1@-470,-2105 -468.47,-2105 -439.61,-2076.14 -423.64,-2076.14 v1(-420,-2072.5) -418.96,-2071.46 -418.96,-2043.96 R364.1@-415,-2040 ; v1@-419.86,-2075.14 -419.86,-2097.56 C257.2@-405,-2112.42
  other v1: -730,-2365 -751.58,-2346.15 -470,-2300 -545,-2225 -620,-2075 -590,-2075 -750,-2000 -720.5,-2000 -750,-1970 -720.5,-1970
-4V_3P: C8.2 C11.2 C95.2 C96.2 C105.2 C111.2 R176.1 R181.1 U3.8 U29.19 U29.20 U29.21 U29.22 U29.23 U29.24 U29.25 U29.26 U29.27 U29.30 U29.31 U29.35 U29.36 | length 196.4
  Bottom Layer w8: R181.1@-471.38,2039 -410.42,2039 C111.2@-405,2033.58 ; C105.2@-471.42,2107 C105.2@-471.42,2107 -408,2107 R176.1@-405,2110 ; C111.2@-405,2045 v1(-405,2075) R176.1@-405,2105
  other v1: -745,1870 -725,1889 -700,2100 -755,2355 -725,2355 -695,2355
-4V_3S: C57.2 C60.2 C206.2 C207.2 C219.2 C226.2 R311.1 R318.1 U18.8 U43.19 U43.20 U43.21 U43.22 U43.23 U43.24 U43.25 U43.26 U43.27 U43.30 U43.31 U43.35 U43.36 | length 196.4
  Bottom Layer w8: R318.1@-471.38,-961 -410.42,-961 C226.2@-405,-966.42 ; C219.2@-471.42,-893 C219.2@-471.42,-893 -408,-893 R311.1@-405,-890 ; C226.2@-405,-955 v1(-405,-925) R311.1@-405,-895
  other v1: -745,-1155 -745,-1125 -700,-900 -755,-645 -725,-645 -695,-645
-4V_4P: C12.2 C93.2 C100.2 C104.2 C107.2 C109.2 R177.1 R182.1 U4.8 U28.19 U28.20 U28.21 U28.22 U28.23 U28.24 U28.25 U28.26 U28.27 U28.30 U28.31 U28.35 U28.36 | length 319
  Bottom Layer w8: C100.2@405,2112.42 419.86,2097.56 v1@419.86,2075.14 ; R182.1@415,2040 418.96,2043.96 418.96,2071.46 v1(420,2072.5) 423.64,2076.14 439.61,2076.14 468.47,2105 R177.1@470,2105 ; v1@425,2065 436.14,2053.86 456.56,2053.86 C109.2@471.42,2039 ; v1(735,2210) 745,2210 769.83,2234.83 784.83,2234.83 U28.31@785,2235 ; v1@745,2211.99 802.15,2211.99 U28.30@804.13,2213.98
  other v1: 720.5,1970 750,1970 720.5,2000 750,2000 590,2075 620,2075 545,2225 470,2300 780,2395 810,2395
-4V_4S: C61.2 C204.2 C216.2 C218.2 C221.2 C223.2 R312.1 R320.1 U19.8 U42.19 U42.20 U42.21 U42.22 U42.23 U42.24 U42.25 U42.26 U42.27 U42.30 U42.31 U42.35 U42.36 | length 354.2
  Bottom Layer w8: C216.2@405,-887.58 419.86,-902.44 v1@419.86,-924.86 ; R320.1@415,-960 418.96,-956.04 418.96,-928.54 v1(420,-927.5) 423.64,-923.86 439.61,-923.86 468.47,-895 R312.1@470,-895 ; v1@425,-935 436.14,-946.14 456.56,-946.14 C223.2@471.42,-961 ; v1(731.86,-772.07) 731.86,-773.98 v1@734.42,-776.54 ; U42.30@804.13,-786.02 744.44,-786.02 734.95,-776.54 v1@734.42,-776.54 ; U42.31@804.13,-760.43 803.98,-760.59 750.37,-760.59 v1@734.42,-776.54
  other v1: 720.5,-1030 750,-1030 720.5,-1000 750,-1000 590,-925 620,-925 545,-775 470,-700 751.58,-653.85 730,-635.5
AIN_1P_NOTUSED: U11.1
AIN_1S_NOTUSED: U25.1
AIN_2P: C150.1 R240.1 U10.1 | length 205.3
  Top Layer w8: v1(-795,595) U10.1@-795,680
  Bottom Layer w8: v1(-795,595) -795,545.58 -793,543.58 -792.96,543.62 R240.1@-725,543.62
AIN_2S: C266.1 R381.1 U24.1 | length 205.3
  Top Layer w8: v1(-795,-2405) U24.1@-795,-2320
  Bottom Layer w8: v1(-795,-2405) -795,-2454.42 -793,-2456.42 -792.96,-2456.38 R381.1@-725,-2456.38
AIN_3P_NOTUSED: U3.1
AIN_3S_NOTUSED: U18.1
AIN_4P_NOTUSED: U4.1
AIN_4S_NOTUSED: U19.1
APWM_P: U10.16 U35.2 | length 927.1
  Top Layer w8: v1(-1613.16,281.84) -1609.52,285.48 -1601.17,285.48 -1211.65,675 U10.16@-1177.78,675
  Bottom Layer w8: U35.2@-1883.75,141.18 -1753.82,141.18 v1(-1613.16,281.84)
APWM_S: U24.16 U35.3 | length 3198.6
  Top Layer w8: v1(-1830,115) -1730,15 v1(-1730,-2380) ; v1(-1510,-2420) -1306.65,-2420 -1211.65,-2325 U24.16@-1177.78,-2325
  Bottom Layer w8: U35.3@-1883.75,115.59 -1883.45,115.3 -1830.3,115.3 v1(-1830,115) ; v1(-1730,-2380) -1550,-2380 v1(-1510,-2420)
B3: R114.2 U9.12 | length 523.7
  Top Layer w8: U9.12@-3042.32,-834.65 -3078.58,-834.65 -3084.44,-840.5 -3100.56,-840.5 -3107.42,-847.36 -3107.42,-1007.58 -3095,-1020 -2833.62,-1020 R114.2@-2823.62,-1030
B4: R117.2 U9.20 | length 701.6
  Top Layer w8: U9.20@-3042.32,-708.66 -3088.66,-708.66 -3123.42,-743.42 -3123.42,-1014.2 -3099.63,-1038 -2886.53,-1038 -2824.53,-1100 R117.2@-2823.62,-1100
CAN_H: C5.2 J12.7 J13.3 L1.3 R14.1 R15.1 | length 1574.6
  Top Layer w8: v1(-6025,3185) -6000,3210 -5750,3210 -5681.42,3278.58 -5463.58,3278.58 ; L1.3@-5189.57,3275.79 -5192.4,3278.62 R15.1@-5282,3278.62 R14.1@-5350,3278.62 R14.1@-5350,3278.62 C5.2@-5418,3278.58 -5433.58,3278.58 -5463.58,3278.58 ; J12.7@-5179.53,3680.91 -5181.2,3680.91 -5280,3582.1 -5280,3545 -5310,3515 -5448.69,3515 -5505.5,3458.19 -5505.5,3320.5 -5463.58,3278.58
  Bottom Layer w8: J13.3@-6075,3155.43 -6063.46,3166.97 -6043.03,3166.97 v1(-6025,3185)
CAN_HFILT: L1.4 U2.7 | length 129.4
  Top Layer w8: L1.4@-5010.43,3275.79 -5001.57,3275.79 -4977.36,3300 U2.7@-4891.09,3300
CAN_L: C3.1 J12.2 J13.4 L1.2 R11.2 R12.2 | length 1377.7
  Top Layer w8: v1(-5480,3360) -5462.5,3377.5 ; J12.2@-5234.06,3569.09 -5234.06,3568.32 -5303.37,3499 -5442.06,3499 -5485,3456.06 -5485,3400 -5462.5,3377.5 ; L1.2@-5189.57,3374.21 -5192.4,3371.38 R12.2@-5282,3371.38 R11.2@-5350,3371.38 R11.2@-5350,3371.38 C3.1@-5418,3371.42 -5456.42,3371.42 -5462.5,3377.5
  Bottom Layer w8: J13.4@-6075,3226.3 -6073.7,3225 -6030,3225 -6015,3210 -5750,3210 -5680,3280 -5515,3280 -5480,3315 v1(-5480,3360)
CAN_LFILT: L1.1 U2.6 | length 129.4
  Top Layer w8: L1.1@-5010.43,3374.21 -5001.57,3374.21 -4977.36,3350 U2.6@-4891.09,3350
CAN_MIDC: C3.2 C5.1 C88.2 | length 186.7
  Top Layer w8: v1(-5435,3180) -5435,3203.47 -5418,3220.47 -5405,3207.47 v1(-5405,3180) ; v1(-5435,3470) -5435,3446.53 -5418,3429.53 -5405,3442.53 v1(-5405,3470)
CAN_MIDR: C88.1 R11.1 R12.1 R14.2 R15.2 | length 237
  Top Layer w8: R14.2@-5350,3221.38 -5336.04,3207.42 -5336.04,3196.19 -5330,3190.14 v1(-5330,3185) v1(-5300,3185) -5300,3190.14 -5295.96,3194.19 -5295.96,3207.42 R15.2@-5282,3221.38 ; R11.1@-5350,3428.62 -5336.04,3442.58 -5336.04,3453.81 -5330,3459.86 v1(-5330,3465) v1(-5300,3465) -5300,3459.86 -5295.96,3455.81 -5295.96,3442.58 R12.1@-5282,3428.62
CAN_RX: U2.4 U9.87 | length 4531.9
  Top Layer w8: U2.4@-4708.91,3400 -4735.04,3400 -4757.71,3377.33 -4757.71,2932.71 -4355,2530 -3500,2530 -3220,2250 -3220,583.44 -3130.5,493.94 -3130.5,405.5 v1(-3130,405) ; U9.87@-2963.58,488.19 -2957.74,482.35 -2927.35,482.35 v1(-2905,460)
  Bottom Layer w8: v1(-3130,405) -3129.5,405.5 -3104.5,405.5 -3040,470 -2919.19,470 -2909.19,460 v1(-2905,460)
CAN_TX: U2.1 U9.88 | length 3988
  Top Layer w8: U2.1@-4708.91,3250 -4708.91,2906.63 -4348.29,2546 -3493.37,2546 -3200,2252.63 -3200,586.06 -3109.44,495.5 -3094.44,495.5 -3087.13,488.19 U9.88@-3042.32,488.19
CLMP_1P: R51.1 U11.7
CLMP_1S: R152.1 U25.7
CLMP_2P: R50.1 U10.7
  other v1: -650,825 -664.5,1015
CLMP_2S: R151.1 U24.7
  other v1: -650,-2175 -664.5,-1985
CLMP_3P: R19.1 U3.7
CLMP_3S: R103.1 U18.7
CLMP_4P: R20.1 U4.7
  other v1: 664.5,1985 648.99,2176.61
CLMP_4S: R104.1 U19.7
  other v1: 664.5,-1015 650,-822.5
D_1S: D26.1 J14.084 | length 500.4
  Top Layer w8: J14.084@50,-1350 60,-1350 318.57,-1608.57 318.57,-1670.77 D26.1@362.8,-1715
D_2P: D10.1 J14.035 | length 418.2
  Top Layer w8: D10.1@-337.8,1297.8 -337.8,1285 -337.8,1272.2 -293.57,1227.98 -227.98,1227.98 J14.035@-50,1050
  Top Layer w10: D10.1@-367.8,1287.2 D10.1@-367.8,1300
D_2S: D25.1 J14.091 | length 340.1
  Top Layer w8: D25.1@-362.8,-1715 -357.8,-1720 -80,-1720 J14.091@-50,-1750
  Top Layer w10: D25.1@-367.8,-1712.8 D25.1@-367.8,-1700
D_3S: D23.1 J14.083 | length 339.7
  Top Layer w8: D23.1@-362.8,-1285 -115,-1285 J14.083@-50,-1350
D_4P: D9.1 J14.019 | length 607.9
  Top Layer w8: J14.019@-45,1850 J14.019@-50,1850 -50,1805.67 -89.36,1766.3 -89.36,1733.7 -66.3,1710.64 342.16,1710.64 D9.1@362.8,1690
D_4S: D24.1 J14.076 | length 498.4
  Top Layer w8: J14.076@50,-950 50,-994.33 89.36,-1033.7 89.36,-1069.36 304.2,-1284.2 361.99,-1284.2 D24.1@362.8,-1285
D_13P: D8.1 D11.1 J14.027 | length 880.3
  Top Layer w8: D8.1@-362.8,1715 -362.8,1702.2 -318.57,1657.98 -257.98,1657.98 J14.027@-50,1450 -37.36,1450 -17.36,1430 160,1430 282.25,1307.75 309.14,1307.75 D11.1@331.89,1285
D_BIAS_1P: D35.2 R35.1 R37.2 | length 222.5
  Top Layer w8: R37.2@843.62,1247 R35.1@843.62,1315 ; R35.1@845,1316.38 v1(845,1365)
  Top Layer w10: R35.1@843.62,1315 R35.1@845,1316.38
  Bottom Layer w10: D35.2@787.2,1285 830.43,1328.23 830.43,1350.43 v1(845,1365)
D_BIAS_1S: D39.2 R139.1 R141.2 | length 222.5
  Top Layer w8: R141.2@843.62,-1753 R139.1@843.62,-1685 ; R139.1@845,-1683.62 v1(845,-1635)
  Top Layer w10: R139.1@843.62,-1685 R139.1@845,-1683.62
  Bottom Layer w10: D39.2@787.2,-1715 830.43,-1671.77 830.43,-1649.57 v1(845,-1635)
D_BIAS_2P: D36.2 R34.1 R36.2 | length 225.1
  Top Layer w8: R36.2@-845,1255 -843.62,1256.38 R34.1@-843.62,1315 -845,1316.38 v1(-845,1370)
  Bottom Layer w8: v1(-845,1370) -841.36,1366.36 -841.36,1351.96 -787.2,1297.8 D36.2@-787.2,1285
D_BIAS_2S: D40.2 R138.1 R140.2 | length 225.1
  Top Layer w8: R140.2@-845,-1745 -843.62,-1743.62 R138.1@-843.62,-1685 -845,-1683.62 v1(-845,-1630)
  Bottom Layer w8: v1(-845,-1630) -841.36,-1633.64 -841.36,-1648.04 -787.2,-1702.2 D40.2@-787.2,-1715
D_BIAS_3P: D34.2 R30.2 R32.1 | length 222.5
  Top Layer w8: v1(-845,1635) R32.1@-845,1683.62 ; R32.1@-843.62,1685 R30.2@-843.62,1753
  Top Layer w10: R32.1@-845,1683.62 R32.1@-843.62,1685
  Bottom Layer w10: v1(-845,1635) -830.43,1649.57 -830.43,1671.77 D34.2@-787.2,1715
D_BIAS_3S: D38.2 R125.2 R129.1 | length 222.5
  Top Layer w8: v1(-845,-1365) R129.1@-845,-1316.38 ; R129.1@-843.62,-1315 R125.2@-843.62,-1247
  Top Layer w10: R129.1@-845,-1316.38 R129.1@-843.62,-1315
  Bottom Layer w10: v1(-845,-1365) -830.43,-1350.43 -830.43,-1328.23 D38.2@-787.2,-1285
D_BIAS_4P: D33.2 R31.2 R33.1 | length 225.1
  Top Layer w8: v1(845,1630) 845,1683.62 R33.1@843.62,1685 843.62,1743.62 R31.2@845,1745
  Bottom Layer w8: D33.2@787.2,1715 787.2,1702.2 841.36,1648.04 841.36,1633.64 v1(845,1630)
D_BIAS_4S: D37.2 R126.2 R130.1 | length 225.1
  Top Layer w8: v1(845,-1370) 845,-1316.38 R130.1@843.62,-1315 843.62,-1256.38 R126.2@845,-1255
  Bottom Layer w8: D37.2@787.2,-1285 787.2,-1297.8 841.36,-1351.96 841.36,-1366.36 v1(845,-1370)
D_MID_1P: D11.2 D35.1 | length 225.5
  Top Layer w8: D11.2@563.6,1286.4 585,1307.8 v1(585,1390)
  Bottom Layer w8: D35.1@563.6,1285.81 585,1307.2 v1(585,1390)
D_MID_1S: D26.2 D39.1 | length 229.7
  Top Layer w8: D26.2@563.6,-1713.6 590,-1687.2 v1(590,-1610)
  Bottom Layer w8: D39.1@563.6,-1714.19 590,-1687.8 v1(590,-1610)
D_MID_2P: D10.2 D36.1 | length 208.1
  Top Layer w8: D10.2@-590,1287.8 v1(-590,1390)
  Bottom Layer w8: v1(-590,1390) -590,1287.2 D36.1@-587.8,1285
D_MID_2S: D25.2 D40.1 | length 208.1
  Top Layer w8: D25.2@-590,-1712.2 v1(-590,-1610)
  Bottom Layer w8: v1(-590,-1610) -590,-1712.8 D40.1@-587.8,-1715
D_MID_3P: D8.2 D34.1 | length 211.2
  Top Layer w8: v1(-590,1610) D8.2@-590,1712.2 ; D8.2@-563.6,1713.6 D8.2@-562.2,1715
  Bottom Layer w8: v1(-590,1610) -590,1712.8 D34.1@-587.8,1715 ; D34.1@-563.6,1714.19 D34.1@-562.8,1715
D_MID_3S: D23.2 D38.1 | length 211.2
  Top Layer w8: v1(-590,-1390) D23.2@-590,-1287.8 ; D23.2@-563.6,-1286.4 D23.2@-562.2,-1285
  Bottom Layer w8: v1(-590,-1390) -590,-1287.2 D38.1@-587.8,-1285 ; D38.1@-563.6,-1285.81 D38.1@-562.8,-1285
D_MID_4P: D9.2 D33.1 | length 221.6
  Top Layer w8: D9.2@565,1712.2 585,1692.2 v1(585,1610)
  Bottom Layer w8: D33.1@565,1712.8 585,1692.8 v1(585,1610)
D_MID_4S: D24.2 D37.1 | length 221.6
  Top Layer w8: D24.2@565,-1287.8 585,-1307.8 v1(585,-1390)
  Bottom Layer w8: D37.1@565,-1287.2 585,-1307.2 v1(585,-1390)
DCDCO_P: C50.2 C53.1 C182.1 U14.1 U14.3 | length 55.5
  Bottom Layer w8: v1(-710,-170) -706.36,-166.36 -699.89,-166.36 -669.53,-136 C182.1@-668.58,-136
DCDCO_S: C38.1 C41.2 C170.1 U15.1 U15.3 | length 50.5
  Bottom Layer w8: C170.1@668.58,136 669.53,136 703.53,170 v1(705,170)
E\R\R\_\1\P\: C163.1 R73.1 U13.2 | length 578.6
  Top Layer w8: v1(-2650,160) -2647.63,160 -2635.81,171.82 -2601.75,171.82 U13.2@-2598.75,174.82 U13.2@-2595.75,171.82 ; v1(-2650,160) -2649.97,139.97 -2566,56 R73.1@-2428.62,56
  Bottom Layer w8: C163.1@-2771.42,328 -2756.92,313.5 -2718.5,313.5 -2675,270 -2675,185 v1(-2650,160)
E\R\R\_\1\P\_\B\U\F\: U9.77 U13.13 | length 242.3
  Top Layer w8: U9.77@-2963.58,330.71 -2957.74,324.87 -2929.94,324.87 -2919.1,314.03 -2919.1,236.54 -2860.38,177.82 -2834.25,177.82 U13.13@-2831.25,174.82
E\R\R\_\1\S\: C160.1 R249.1 U36.2 | length 874
  Top Layer w8: v1(-3240,90.09) -3220,110.09 -3220,274.58 -3129.58,365 v1(-3125,365)
  Bottom Layer w8: v1(-3240,90.09) -3180.09,150 -3149.86,150 -3140.45,140.59 -3084.34,140.59 U36.2@-3083.75,141.18 -3016.35,141.18 -2897.53,260 R249.1@-2828.62,260 ; C160.1@-3171.42,396 -3170.47,396 -3154.66,380.19 -3145.33,380.19 -3130.14,365 v1(-3125,365)
E\R\R\_\1\S\_\B\U\F\: U9.78 U36.13 | length 395.9
  Top Layer w8: v1(-3125,325) -3122.15,327.85 -3045.18,327.85 U9.78@-3042.32,330.71
  Bottom Layer w8: U36.13@-3316.25,141.18 -3234.6,141.18 -3139.61,236.17 -3139.61,305.25 -3125,319.86 v1(-3125,325)
E\R\R\_\2\P\: C159.1 R68.1 U13.3 | length 471.6
  Top Layer w8: v1(-2649.5,200) -2649.3,200.2 -2598.95,200.2 U13.3@-2598.75,200.41 -2437.03,200.41 R68.1@-2428.62,192
  Bottom Layer w8: C159.1@-2771.42,396 -2770.47,396 -2650,275.53 -2650,200.5 v1(-2649.5,200)
E\R\R\_\2\P\_\B\U\F\: U9.79 U13.12 | length 248.2
  Top Layer w8: U9.79@-2963.58,362.2 -2957.74,356.36 -2929.94,356.36 -2903,329.42 -2903,246.03 -2860.38,203.41 -2834.25,203.41 U13.12@-2831.25,200.41
E\R\R\_\2\S\: C179.1 R254.1 U36.3 | length 541.6
  Bottom Layer w8: C179.1@-3171.42,-80 -3171.42,-46.82 -3177.08,-41.17 -3177.08,6.46 -3172.5,11.04 -3172.5,52.97 -3112.88,112.59 -3086.75,112.59 U36.3@-3083.75,115.59 -3016.97,115.59 -2937.06,195.5 -2873.77,195.5 -2870.27,192 R254.1@-2828.62,192
E\R\R\_\2\S\_\B\U\F\: U9.80 U36.12 | length 465.3
  Top Layer w8: v1(-3090.4,384.09) -3086.1,384.09 -3073.87,371.86 -3068.71,371.86 -3059.06,362.2 U9.80@-3042.32,362.2
  Bottom Layer w8: U36.12@-3316.25,115.59 -3237.56,115.59 -3123.61,229.54 -3123.61,289.83 -3090.4,323.04 v1(-3090.4,384.09)
E\R\R\_\3\P\: C154.1 R63.1 U13.4 | length 569.9
  Top Layer w8: U13.4@-2598.75,226 -2597,227.75 -2551.75,227.75 v1(-2550,229.5) ; v1@-2549.5,229.5 -2460.03,229.5 -2429.53,260 R63.1@-2428.62,260
  Bottom Layer w8: C154.1@-2771.42,464 -2770.47,464 -2703.54,397.07 -2602.07,397.07 -2550,345 v1(-2550,229.5)
E\R\R\_\3\P\_\B\U\F\: U9.81 U13.11 | length 254.1
  Top Layer w8: U9.81@-2963.58,393.7 -2957.74,387.86 -2929.94,387.86 -2887,344.92 -2887,255.62 -2860.38,229 -2834.25,229 U13.11@-2831.25,226
E\R\R\_\3\S\: C183.1 R257.1 U36.4 | length 581.7
  Bottom Layer w8: C183.1@-3171.42,-148 -3170.47,-148 -3139.61,-117.14 -3139.61,-56.01 -3161.08,-34.54 -3161.08,-0.16 -3156.5,4.41 -3156.5,43.38 -3112.88,87 -3086.75,87 U36.4@-3083.75,90 -2982.27,90 -2976.77,84.5 -2901.71,84.5 -2862.21,124 R257.1@-2828.62,124
E\R\R\_\3\S\_\B\U\F\: U9.91 U36.11 | length 910.9
  Top Layer w8: U9.91@-2963.58,551.18 -2940.94,551.18 -2931.29,541.53 -2926.13,541.53 -2913.33,528.72 -2913.33,511.52 v1(-2909.69,507.88)
  Bottom Layer w8: U36.11@-3316.25,90 -3319.25,93 -3345.38,93 -3360,107.62 -3360,370 -3296.86,433.14 -3105.8,433.14 -3079.5,459.44 -3079.5,473.41 -3064.72,488.19 -2931.81,488.19 -2912.12,507.88 v1(-2909.69,507.88)
E\R\R\_\4\P\: C151.1 R62.1 U13.5 | length 621.9
  Top Layer w8: U13.5@-2598.75,251.59 -2596.25,254.09 -2564.09,254.09 -2563.18,255 v1(-2524.5,255) ; v1@-2525,255 -2521.97,258.03 -2499.5,258.03 -2429.53,328 R62.1@-2428.62,328
  Bottom Layer w8: C151.1@-2771.42,532 -2702.47,532 -2525,354.53 -2525,255.5 v1(-2524.5,255)
E\R\R\_\4\P\_\B\U\F\: U9.76 U13.10 | length 495.2
  Top Layer w8: v1(-3091.7,277.72) -3090.02,277.72 -3073.54,294.2 -3047.33,294.2 U9.76@-3042.32,299.21 ; v1(-2890,390) -2871,371 -2871,265.21 -2860.38,254.59 -2834.25,254.59 U13.10@-2831.25,251.59
  Bottom Layer w8: v1(-3091.7,277.72) -3090.27,277.72 -3042.13,325.87 -3042.13,344.07 -2996.19,390 v1(-2890,390)
E\R\R\_\4\S\: C185.1 R261.1 U36.5 | length 623.1
  Bottom Layer w8: C185.1@-3171.42,-216 -3170.47,-216 -3139.42,-184.95 -3139.42,-139.58 -3123.61,-123.76 -3123.61,-49.38 -3145.08,-27.91 -3145.08,-6.79 -3140.5,-2.21 -3140.5,33.79 -3112.88,61.41 -3086.75,61.41 U36.5@-3083.75,64.41 -2983.04,64.41 -2957.63,39 -2891.71,39 -2874.71,56 R261.1@-2828.62,56
E\R\R\_\4\S\_\B\U\F\: U9.92 U36.10 | length 791
  Top Layer w8: v1(-3120,555) -3118.09,553.09 -3044.23,553.09 U9.92@-3042.32,551.18
  Bottom Layer w8: U36.10@-3316.25,64.41 -3319.25,67.41 -3347.41,67.41 -3380,100 -3380,390 -3272.02,497.98 -3151.61,497.98 -3120.09,529.5 -3120.09,554.91 v1(-3120,555)
EPWM8A: R119.2 U9.62 | length 1594.4
  Top Layer w8: U9.62@-3055,80 -3057.8,80 -3068.71,69.09 -3073.87,69.09 -3080.9,62.06 -3080.9,9.59 -3080.9,0.94 -3030,-49.96 -3030,-97.46 -3044.04,-111.5 -3111.5,-111.5 -3140,-140 -3140,-1020.25 -3106.25,-1054 -2976,-1054 -2862,-1168 R119.2@-2828.62,-1168
EPWM8B: R123.2 U9.64 | length 1705.2
  Top Layer w8: U9.64@-3042.32,110.24 -3059.06,110.24 -3068.71,100.58 -3073.87,100.58 -3096.9,77.55 -3096.9,-5.69 -3046,-56.59 -3046,-90.81 -3050.69,-95.5 -3109.19,-95.5 -3118.13,-95.5 -3156,-133.37 -3156,-1026.88 -3112.88,-1070 -2982.63,-1070 -2950,-1102.63 -2950,-1123.94 -2900.95,-1172.99 -2892.54,-1172.99 -2829.53,-1236 R123.2@-2828.62,-1236
F\L\T\_\1\P\: R199.2 R206.1 U11.13 | length 1167.9
  Top Layer w8: U11.13@1177.78,875 1211.65,875 1232.15,854.5 1291.65,854.5 1308.15,871 1446,871 1480,905 1480,1081.66 1480.23,1081.89 1480.23,1103.02 1480,1103.25 1480,1190 1475.73,1194.27 v1(1470,1188.54) 1432.45,1226.09 1313.91,1226.09 1280,1260 1280,1325.56 1265.5,1340.06 v1(1265.5,1385.31)
  Bottom Layer w8: v1(1265.5,1385.31) 1283.76,1403.57 1283.76,1408.76 1305,1430 1339.38,1430 R199.2@1341.38,1432 ; R206.1@1398.62,1228 1399.53,1228 1438.98,1188.54 v1(1470,1188.54)
F\L\T\_\1\S\: R345.2 R356.1 U25.13 | length 1455.4
  Top Layer w8: U25.13@1177.78,-2125 1211.65,-2125 1232.15,-2145.5 1291.65,-2145.5 1325.28,-2111.86 1424.36,-2111.86 1430.39,-2117.9 1456.57,-2117.9 v1(1458.07,-2116.39) ; v1(1285,-1560) 1285,-1638.94 1305.5,-1659.44 1305.5,-1680.56 1285.56,-1700.5 1250.21,-1700.5 1240,-1710.71 1240,-1745 1255,-1760 1278.84,-1760 1289.92,-1748.92 1401.29,-1748.92 1449.35,-1796.98 1449.35,-1819.3 v1(1452.52,-1822.48)
  Bottom Layer w8: v1(1285,-1560) 1333.38,-1560 R345.2@1341.38,-1568 ; R356.1@1398.62,-1772 1403.92,-1777.3 1424.8,-1777.3 1440.52,-1793.02 1440.52,-1805.33 1452.52,-1817.34 1452.52,-1827.62 1467.53,-1842.63 1467.53,-1867.53 1535,-1935 1582.5,-1935 1612,-1964.5 1612,-2038 1532.66,-2117.34 1459.02,-2117.34 v1(1458.07,-2116.39)
F\L\T\_\2\P\: R200.2 R202.1 U10.13 | length 1361.2
  Top Layer w8: v1(-1615,1195.5) -1615,1194.94 -1641.5,1168.44 -1641.5,953.87 -1492.63,805 -1335,805 -1302.86,837.14 -1300.01,837.14 -1291.65,845.5 -1232.15,845.5 -1211.65,825 U10.13@-1177.78,825
  Bottom Layer w8: v1(-1615,1195.5) -1614.5,1195 -1438.69,1195 -1378.69,1255 -1303.94,1255 -1274.5,1284.44 -1274.5,1305.56 -1296.74,1327.8 -1304.28,1327.8 -1340.47,1364 R202.1@-1341.38,1364 R200.2@-1341.38,1432
F\L\T\_\2\S\: R346.2 R350.1 U24.13 | length 1144
  Top Layer w8: v1(-1471.06,-2193.94) -1469,-2196 -1445.56,-2196 -1441.56,-2200 -1337.66,-2200 -1300.52,-2162.86 -1300.01,-2162.86 -1287.15,-2150 -1236.65,-2150 -1211.65,-2175 U24.13@-1177.78,-2175
  Bottom Layer w8: v1(-1471.06,-2193.94) -1467.43,-2190.3 -1467.43,-2177.89 -1464.5,-2174.96 -1464.5,-2154.44 -1528.62,-2090.32 -1528.62,-1848.62 -1500,-1820 -1401.78,-1820 -1309.61,-1727.83 -1309.61,-1666.86 -1340.47,-1636 R350.1@-1341.38,-1636 R346.2@-1341.38,-1568
F\L\T\_\3\P\: R189.1 R196.2 U3.13 | length 1144.6
  Top Layer w8: v1(-1506.5,2105) -1332.15,2105 -1291.65,2145.5 -1232.15,2145.5 -1211.65,2125 U3.13@-1177.78,2125 ; v1(-1299.3,1756.9) -1299.3,1655.6 -1289.5,1645.8 -1289.5,1615.34 -1280,1605.84 v1(-1280,1535)
  Bottom Layer w8: v1(-1506.5,2105) -1506.5,1998.93 -1500,1992.43 -1500,1869.33 -1467.63,1836.96 -1464.21,1836.96 -1460.75,1833.5 -1456.46,1833.5 -1427.96,1805 -1375.28,1805 -1342.28,1772 R189.1@-1341.38,1772 -1327.42,1758.04 -1322.97,1758.04 -1321.83,1756.9 v1(-1299.3,1756.9) ; R196.2@-1341.38,1568 -1313,1568 v1(-1280,1535)
F\L\T\_\3\S\: R328.1 R340.2 U18.13 | length 1160.2
  Top Layer w8: v1@-1480.94,-1181.29 -1477.82,-1184.41 -1477.82,-1197.18 -1455,-1220 -1404.95,-1220 -1320.5,-1304.45 -1320.5,-1335.56 -1290,-1366.06 v1(-1290,-1465) ; v1(-1480.27,-1180.63) -1500.5,-1160.4 -1500.5,-963.65 -1451.32,-914.47 -1450.53,-914.47 -1398.93,-862.86 -1300.01,-862.86 -1291.65,-854.5 -1232.15,-854.5 -1211.65,-875 U18.13@-1177.78,-875
  Bottom Layer w8: v1(-1480.27,-1180.63) -1478.41,-1182.49 -1463.1,-1182.49 -1429.98,-1215.61 -1411.01,-1215.61 R328.1@-1398.62,-1228 ; R340.2@-1341.38,-1432 -1327.42,-1445.96 -1309.04,-1445.96 v1(-1290,-1465)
